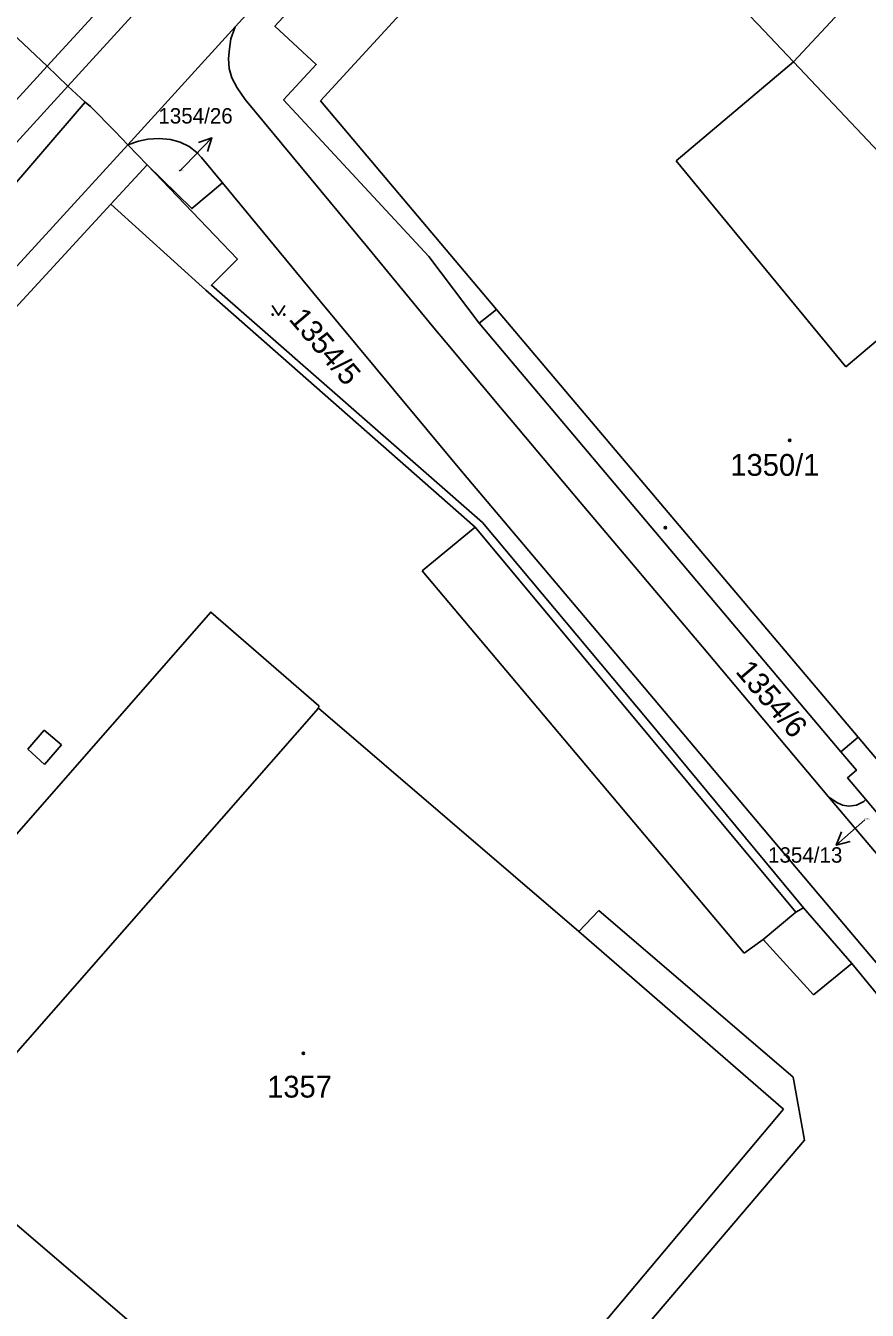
# Model space of a CAD drawing. Extents: x -598934 to -598196, y -1162208 to -1161502.
# Drawn here: x -598445.3 to -598379.6, y -1161704.6 to -1161604.5 of the extents above; entities that cross this region are included whole.
import ezdxf

# ---------------------------------------------------------------- set-up
doc = ezdxf.new("R2010")
doc.units = 0
for name, color, linetype in [('KN_CAR_KR', 7, 'Continuous'), ('KN_KULTURY', 7, 'Continuous'), ('KN_PARC_CIS_POM', 7, 'Continuous'), ('KN_PARC_CIS_POZ', 7, 'Continuous'), ('KN_PARC_CIS_STAV', 7, 'Continuous'), ('KN_PARC_PLOCHA', 7, 'Continuous'), ('PARC_C_SIPKA', 7, 'Continuous'), ('parcely_l', 7, 'Continuous')]:
    doc.layers.add(name, color=color, linetype=linetype)

msp = doc.modelspace()

# ---------------------------------------------------------------- linework, layer by layer
at = {"layer": 'KN_CAR_KR'}
for points in [[(-598402.81, -1161589.15), (-598422.29, -1161610.35)], [(-598385.4, -1161607.3), (-598379.65, -1161601.12)], [(-598394.54, -1161615.01), (-598385.4, -1161607.3)], [(-598422.29, -1161610.35), (-598408.55, -1161626.6)], [(-598381.33, -1161631.07), (-598394.54, -1161615.01)], [(-598438.63, -1161618.4), (-598431.22, -1161625.09)], [(-598431.22, -1161625.09), (-598410.22, -1161643.56)], [(-598408.55, -1161626.6), (-598409.91, -1161627.67)], [(-598408.55, -1161626.6), (-598380.37, -1161659.94)], [(-598378.28, -1161628.49), (-598381.33, -1161631.07)], [(-598414.37, -1161646.98), (-598410.22, -1161643.56)], [(-598410.22, -1161643.56), (-598385.21, -1161673.58)], [(-598389.26, -1161676.78), (-598414.37, -1161646.98)], [(-598422.44, -1161657.68), (-598452.73, -1161692.19)], [(-598445.1, -1161660.88), (-598443.84, -1161659.4)], [(-598443.84, -1161659.4), (-598442.48, -1161660.53)], [(-598442.48, -1161660.53), (-598443.81, -1161662.08)], [(-598380.37, -1161659.94), (-598381.71, -1161661.08)], [(-598380.37, -1161659.94), (-598364.85, -1161678.3)], [(-598443.81, -1161662.08), (-598445.1, -1161660.88)], [(-598402.15, -1161675.09), (-598400.58, -1161673.46)], [(-598400.58, -1161673.46), (-598385.42, -1161686.44)], [(-598385.21, -1161673.58), (-598387.76, -1161675.7)], [(-598385.21, -1161673.58), (-598384.62, -1161673.23)], [(-598387.76, -1161675.7), (-598389.26, -1161676.78)], [(-598383.85, -1161680.03), (-598387.76, -1161675.7)], [(-598380.84, -1161677.59), (-598383.85, -1161680.03)], [(-598385.42, -1161686.44), (-598384.54, -1161691.34)], [(-598384.54, -1161691.34), (-598413.43, -1161725.26)]]:
    msp.add_lwpolyline(points, dxfattribs=at)
at = {"layer": 'KN_KULTURY'}
msp.add_lwpolyline([(-598426.06, -1161626.3), (-598425.56, -1161627.05), (-598425.06, -1161626.3)], dxfattribs=at)
for centre, radius in [((-598426.01, -1161627), 0.05), ((-598425.11, -1161627), 0.05), ((-598385.69, -1161636.81), 0.09), ((-598385.69, -1161636.81), 0.0398), ((-598395.39, -1161643.6), 0.09), ((-598395.39, -1161643.6), 0.0398), ((-598423.62, -1161684.58), 0.09), ((-598423.62, -1161684.58), 0.0398)]:
    msp.add_circle(centre, radius, dxfattribs=at)
at = {"layer": 'KN_PARC_PLOCHA'}
for points in [[(-598415.2, -1161576.69), (-598443.61, -1161607.65), (-598447.76, -1161603.75), (-598420.31, -1161573.75), (-598419.3, -1161572.65)], [(-598335.08, -1161630.46), (-598323.26, -1161644.05), (-598334.82, -1161665.7), (-598338.44, -1161661.36), (-598341.1, -1161658.12), (-598350.93, -1161646.15), (-598351.03, -1161646.03), (-598365.81, -1161628.03), (-598385.4, -1161607.3), (-598388.18, -1161604.36), (-598396.66, -1161595.57), (-598402.81, -1161589.15), (-598388.6, -1161574.13), (-598370.8, -1161592.1), (-598369.55, -1161593.36), (-598366.15, -1161596.79), (-598341.89, -1161623.08), (-598341.18, -1161623.85)], [(-598413.64, -1161578.21), (-598414.79, -1161579.46), (-598441.98, -1161609.19), (-598443.61, -1161607.65), (-598415.2, -1161576.69)], [(-598412.69, -1161579.19), (-598409.16, -1161582.73), (-598409.04, -1161582.85), (-598413.71, -1161587.96), (-598428.93, -1161604.58), (-598437.32, -1161613.76), (-598438.3, -1161612.74), (-598440.23, -1161610.79), (-598440.63, -1161610.45), (-598441.98, -1161609.19), (-598414.79, -1161579.46), (-598413.64, -1161578.21), (-598413.34, -1161578.49)], [(-598443.61, -1161607.65), (-598450.63, -1161615.3), (-598450.33, -1161615.61), (-598497.15, -1161666.75), (-598499.48, -1161669.29), (-598504.18, -1161664.78), (-598501.41, -1161661.76), (-598455.16, -1161611.23), (-598454.84, -1161611.48), (-598447.76, -1161603.75)], [(-598441.98, -1161609.19), (-598452.99, -1161621.22), (-598496.1, -1161668.36), (-598498.13, -1161670.59), (-598499.48, -1161669.29), (-598497.15, -1161666.75), (-598450.33, -1161615.61), (-598450.63, -1161615.3), (-598443.61, -1161607.65)], [(-598440.63, -1161610.45), (-598487.2, -1161664.63), (-598493.87, -1161672.5), (-598494.79, -1161673.79), (-598498.13, -1161670.59), (-598496.1, -1161668.36), (-598452.99, -1161621.22), (-598441.98, -1161609.19)], [(-598437.32, -1161613.76), (-598448.19, -1161625.65), (-598493.45, -1161675.07), (-598494.79, -1161673.79), (-598493.87, -1161672.5), (-598487.2, -1161664.63), (-598440.63, -1161610.45), (-598440.23, -1161610.79), (-598438.3, -1161612.74)], [(-598429.93, -1161616.73), (-598432.33, -1161618.74), (-598435.81, -1161615.34), (-598437.32, -1161613.76), (-598436.49, -1161613.48), (-598435.74, -1161613.33), (-598434.86, -1161613.27), (-598433.99, -1161613.36), (-598433.22, -1161613.57), (-598432.52, -1161613.9), (-598431.93, -1161614.38), (-598431.56, -1161614.75)], [(-598435.81, -1161615.34), (-598438.63, -1161618.4), (-598492.06, -1161676.4), (-598493.45, -1161675.07), (-598448.19, -1161625.65), (-598437.32, -1161613.76)], [(-598386.18, -1161688.92), (-598402.15, -1161675.09), (-598422.44, -1161657.68), (-598422.42, -1161657.49), (-598430.84, -1161650.19), (-598461.34, -1161685.01), (-598452.94, -1161692.42), (-598452.73, -1161692.19), (-598429.74, -1161711.85), (-598415.67, -1161724.01)], [(-598386.18, -1161688.92), (-598415.67, -1161724.01), (-598429.74, -1161711.85), (-598452.73, -1161692.19), (-598452.94, -1161692.42), (-598461.34, -1161685.01), (-598430.84, -1161650.19), (-598422.42, -1161657.49), (-598422.44, -1161657.68), (-598402.15, -1161675.09)], [(-598379.76, -1161664.8), (-598378.12, -1161666.75), (-598378.64, -1161667.32), (-598378.89, -1161668.03), (-598378.85, -1161668.8), (-598378.51, -1161669.49), (-598382.66, -1161664.58), (-598382.03, -1161665.02), (-598381.58, -1161665.23), (-598381.08, -1161665.32), (-598380.48, -1161665.24), (-598379.91, -1161664.94)]]:
    msp.add_lwpolyline(points, close=True, dxfattribs=at)
for points in [[(-598410.3, -1161587.66), (-598425.84, -1161604.52), (-598422.62, -1161607.5), (-598425.16, -1161610.26), (-598413.85, -1161622.48), (-598409.91, -1161627.67), (-598381.71, -1161661.08), (-598380.5, -1161662.52), (-598381.19, -1161663.11), (-598379.76, -1161664.8), (-598379.91, -1161664.94), (-598380.48, -1161665.24), (-598381.08, -1161665.32), (-598381.58, -1161665.23), (-598382.03, -1161665.02), (-598382.66, -1161664.58), (-598391.54, -1161654.04), (-598392.51, -1161652.9), (-598396.79, -1161647.84), (-598397.75, -1161646.7), (-598402.03, -1161641.63), (-598403.01, -1161640.48), (-598407.26, -1161635.41), (-598408.26, -1161634.25), (-598412.48, -1161629.18), (-598413.44, -1161628.03), (-598417.67, -1161622.92), (-598418.62, -1161621.76), (-598428.16, -1161610.24), (-598428.78, -1161609.32), (-598429.2, -1161608.56), (-598429.4, -1161607.81), (-598429.45, -1161607.04), (-598429.39, -1161606.29), (-598429.27, -1161605.52), (-598428.93, -1161604.58), (-598413.71, -1161587.96)], [(-598388.18, -1161604.36), (-598385.4, -1161607.3), (-598365.81, -1161628.03), (-598351.03, -1161646.03), (-598350.93, -1161646.15), (-598341.1, -1161658.12), (-598356.42, -1161671.14), (-598354.76, -1161673.11), (-598363.27, -1161680.35), (-598366.25, -1161676.82), (-598367.43, -1161677.86), (-598373.24, -1161670.97), (-598374, -1161671.63), (-598378.12, -1161666.75), (-598379.76, -1161664.8), (-598381.19, -1161663.11), (-598380.5, -1161662.52), (-598381.71, -1161661.08), (-598409.91, -1161627.67), (-598413.85, -1161622.48), (-598425.16, -1161610.26), (-598422.62, -1161607.5), (-598425.84, -1161604.52), (-598410.3, -1161587.66)], [(-598372.65, -1161684.98), (-598387.27, -1161667.65), (-598395.91, -1161657.42), (-598401.07, -1161651.3), (-598411.41, -1161639.04), (-598416.57, -1161632.87), (-598422.32, -1161625.96), (-598429.93, -1161616.73), (-598431.56, -1161614.75), (-598431.93, -1161614.38), (-598432.52, -1161613.9), (-598433.22, -1161613.57), (-598433.99, -1161613.36), (-598434.86, -1161613.27), (-598435.74, -1161613.33), (-598436.49, -1161613.48), (-598437.32, -1161613.76), (-598428.93, -1161604.58), (-598429.27, -1161605.52), (-598429.39, -1161606.29), (-598429.45, -1161607.04), (-598429.4, -1161607.81), (-598429.2, -1161608.56), (-598428.78, -1161609.32), (-598428.16, -1161610.24), (-598418.62, -1161621.76), (-598417.67, -1161622.92), (-598413.44, -1161628.03), (-598412.48, -1161629.18), (-598408.26, -1161634.25), (-598407.26, -1161635.41), (-598403.01, -1161640.48), (-598402.03, -1161641.63), (-598397.75, -1161646.7), (-598396.79, -1161647.84), (-598392.51, -1161652.9), (-598391.54, -1161654.04), (-598382.66, -1161664.58), (-598378.51, -1161669.49)], [(-598492.06, -1161676.4), (-598438.63, -1161618.4), (-598435.81, -1161615.34), (-598428.76, -1161622.69), (-598430.79, -1161624.72), (-598409.66, -1161643.2), (-598396.69, -1161658.7), (-598384.62, -1161673.23), (-598380.84, -1161677.59), (-598359.36, -1161703.7), (-598368.4, -1161709.66), (-598370.21, -1161711.06), (-598373.51, -1161714.16), (-598376.07, -1161708.98), (-598386.82, -1161714.43), (-598384.3, -1161719.62), (-598389.25, -1161722.01), (-598401.62, -1161728.95), (-598413, -1161741.14), (-598426.83, -1161755.55), (-598427.55, -1161756.32), (-598440.02, -1161777.77)], [(-598359.36, -1161703.7), (-598380.84, -1161677.59), (-598384.62, -1161673.23), (-598396.69, -1161658.7), (-598409.66, -1161643.2), (-598430.79, -1161624.72), (-598428.76, -1161622.69), (-598435.81, -1161615.34), (-598432.33, -1161618.74), (-598429.93, -1161616.73), (-598422.32, -1161625.96), (-598416.57, -1161632.87), (-598411.41, -1161639.04), (-598401.07, -1161651.3), (-598395.91, -1161657.42), (-598387.27, -1161667.65), (-598372.65, -1161684.98)]]:
    msp.add_lwpolyline(points, dxfattribs=at)
at = {"layer": 'PARC_C_SIPKA'}
for points in [[(-598433.28, -1161615.82), (-598432.85, -1161615.38), (-598430.75, -1161613.23)], [(-598431.81, -1161613.6), (-598430.75, -1161613.23), (-598431.09, -1161614.3)], [(-598379.83, -1161666.37), (-598382.07, -1161668.36)], [(-598380.99, -1161668.07), (-598382.07, -1161668.36), (-598381.66, -1161667.32)]]:
    msp.add_lwpolyline(points, dxfattribs=at)
at = {"layer": 'parcely_l'}
for points in [[(-598443.61, -1161607.65), (-598415.2, -1161576.69)], [(-598413.64, -1161578.21), (-598414.79, -1161579.46), (-598441.98, -1161609.19)], [(-598413.71, -1161587.96), (-598428.93, -1161604.58)], [(-598379.76, -1161664.8), (-598381.19, -1161663.11), (-598380.5, -1161662.52), (-598381.71, -1161661.08), (-598409.91, -1161627.67), (-598413.85, -1161622.48), (-598425.16, -1161610.26), (-598422.62, -1161607.5), (-598425.84, -1161604.52), (-598410.3, -1161587.66)], [(-598341.1, -1161658.12), (-598350.93, -1161646.15), (-598351.03, -1161646.03), (-598365.81, -1161628.03), (-598385.4, -1161607.3), (-598388.18, -1161604.36), (-598396.66, -1161595.57), (-598402.81, -1161589.15)], [(-598447.76, -1161603.75), (-598443.61, -1161607.65)], [(-598437.32, -1161613.76), (-598428.93, -1161604.58)], [(-598428.93, -1161604.58), (-598429.27, -1161605.52), (-598429.39, -1161606.29), (-598429.45, -1161607.04), (-598429.4, -1161607.81), (-598429.2, -1161608.56), (-598428.78, -1161609.32), (-598428.16, -1161610.24), (-598418.62, -1161621.76), (-598417.67, -1161622.92), (-598413.44, -1161628.03), (-598412.48, -1161629.18), (-598408.26, -1161634.25), (-598407.26, -1161635.41), (-598403.01, -1161640.48), (-598402.03, -1161641.63), (-598397.75, -1161646.7), (-598396.79, -1161647.84), (-598392.51, -1161652.9), (-598391.54, -1161654.04), (-598382.66, -1161664.58)], [(-598443.61, -1161607.65), (-598450.63, -1161615.3), (-598450.33, -1161615.61), (-598497.15, -1161666.75), (-598499.48, -1161669.29)], [(-598441.98, -1161609.19), (-598443.61, -1161607.65)], [(-598498.13, -1161670.59), (-598496.1, -1161668.36), (-598452.99, -1161621.22), (-598441.98, -1161609.19)], [(-598441.98, -1161609.19), (-598440.63, -1161610.45)], [(-598440.63, -1161610.45), (-598487.2, -1161664.63), (-598493.87, -1161672.5), (-598494.79, -1161673.79)], [(-598440.63, -1161610.45), (-598440.23, -1161610.79), (-598438.3, -1161612.74), (-598437.32, -1161613.76)], [(-598437.32, -1161613.76), (-598436.49, -1161613.48), (-598435.74, -1161613.33), (-598434.86, -1161613.27), (-598433.99, -1161613.36), (-598433.22, -1161613.57), (-598432.52, -1161613.9), (-598431.93, -1161614.38), (-598431.56, -1161614.75), (-598429.93, -1161616.73)], [(-598493.45, -1161675.07), (-598448.19, -1161625.65), (-598437.32, -1161613.76)], [(-598437.32, -1161613.76), (-598435.81, -1161615.34)], [(-598435.81, -1161615.34), (-598438.63, -1161618.4), (-598492.06, -1161676.4)], [(-598429.93, -1161616.73), (-598432.33, -1161618.74), (-598435.81, -1161615.34)], [(-598359.36, -1161703.7), (-598380.84, -1161677.59), (-598384.62, -1161673.23), (-598396.69, -1161658.7), (-598409.66, -1161643.2), (-598430.79, -1161624.72), (-598428.76, -1161622.69), (-598435.81, -1161615.34)], [(-598356.81, -1161695.16), (-598353.96, -1161698.52), (-598358.15, -1161702.12), (-598372.65, -1161684.98), (-598387.27, -1161667.65), (-598395.91, -1161657.42), (-598401.07, -1161651.3), (-598411.41, -1161639.04), (-598416.57, -1161632.87), (-598422.32, -1161625.96), (-598429.93, -1161616.73)], [(-598386.18, -1161688.92), (-598415.67, -1161724.01), (-598429.74, -1161711.85), (-598452.73, -1161692.19), (-598452.94, -1161692.42), (-598461.34, -1161685.01), (-598430.84, -1161650.19), (-598422.42, -1161657.49), (-598422.44, -1161657.68), (-598402.15, -1161675.09), (-598386.18, -1161688.92)], [(-598382.66, -1161664.58), (-598378.51, -1161669.49)], [(-598379.76, -1161664.8), (-598379.91, -1161664.94), (-598380.48, -1161665.24), (-598381.08, -1161665.32), (-598381.58, -1161665.23), (-598382.03, -1161665.02), (-598382.66, -1161664.58)], [(-598378.12, -1161666.75), (-598379.76, -1161664.8)]]:
    msp.add_lwpolyline(points, dxfattribs=at)

# ---------------------------------------------------------------- texts
at = {"layer": 'KN_PARC_CIS_POM'}
for s, p in [('1354/26', (-598433.44, -1161615.82)), ('1354/13', (-598379.99, -1161666.37))]:
    msp.add_text(s, height=0.1, dxfattribs=at).set_placement(p)
at = {"layer": 'KN_PARC_CIS_POZ'}
for s, p in [('1354/26', (-598434.93, -1161612.11)), ('1354/13', (-598387.39, -1161669.72))]:
    msp.add_text(s, height=1.2, dxfattribs=at).set_placement(p)
for s, p in [('1354/5', (-598424.82, -1161627.38)), ('1354/6', (-598389.99, -1161654.85))]:
    msp.add_text(s, height=1.7, rotation=310.5006, dxfattribs=at).set_placement(p)
at = {"layer": 'KN_PARC_CIS_STAV'}
for s, p in [('1350/1', (-598390.33, -1161639.57)), ('1357', (-598426.45, -1161688.03))]:
    msp.add_text(s, height=1.7, dxfattribs=at).set_placement(p)

doc.saveas('drawing.dxf')
